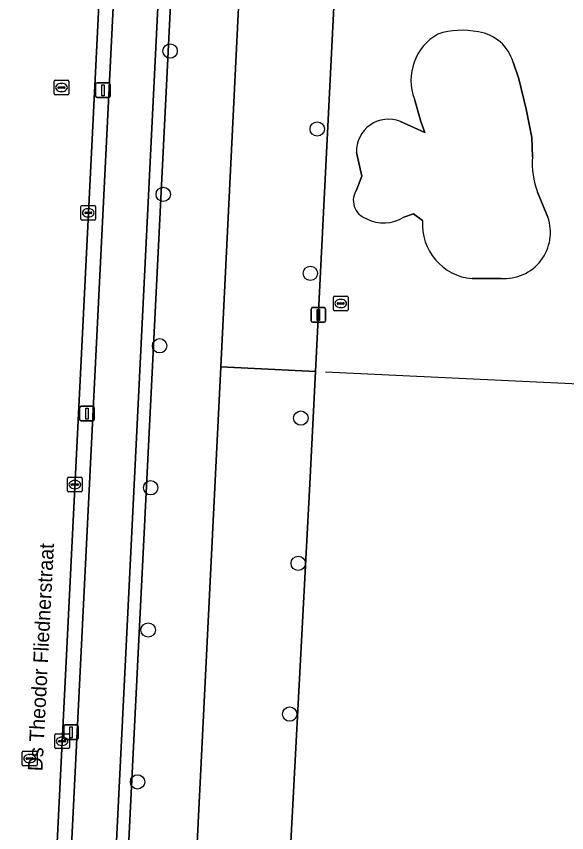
# Model space of a CAD drawing. Extents: x 161758 to 162722, y 384793 to 385405.
# Drawn here: x 162119.5 to 162156.9, y 385099.1 to 385154.7 of the extents above; entities that cross this region are included whole.
import ezdxf

# ---------------------------------------------------------------- set-up
doc = ezdxf.new("R2010")
doc.units = 0
for name, color, linetype in [('IMGEO_Boom', 7, 'Continuous'), ('IMGEO_Brandkraan', 7, 'Continuous'), ('IMGEO_Fietspad_gesloten', 7, 'Continuous'), ('IMGEO_Groenvoorziening', 7, 'Continuous'), ('IMGEO_Hek', 7, 'Continuous'), ('IMGEO_Kolk', 7, 'Continuous'), ('IMGEO_Lichtmast', 7, 'Continuous'), ('IMGEO_Openbare_ruimte_label', 7, 'Continuous'), ('IMGEO_Rijbaan_lokaal_gesloten', 7, 'Continuous'), ('IMGEO_Rioolput', 7, 'Continuous'), ('IMGEO_Verkeerseiland_open', 7, 'Continuous')]:
    doc.layers.add(name, color=color, linetype=linetype)

msp = doc.modelspace()

# ---------------------------------------------------------------- linework, layer by layer
at = {"layer": 'IMGEO_Boom'}
for centre in [(162129.924, 385152.338), (162139.937, 385147.029), (162129.455, 385142.578), (162139.469, 385137.203), (162129.208, 385132.263), (162138.822, 385127.34), (162128.599, 385122.593), (162138.645, 385117.45), (162128.431, 385112.904), (162138.061, 385107.18), (162127.706, 385102.563)]:
    msp.add_circle(centre, 0.489, dxfattribs=at)
at = {"layer": 'IMGEO_Brandkraan'}
for p, q in [((162141.037, 385134.723), (162141.037, 385135.575)), ((162141.112, 385135.649), (162141.964, 385135.649)), ((162142.038, 385135.575), (162142.038, 385134.723)), ((162141.296, 385135.143), (162141.296, 385135.155)), ((162141.734, 385135.106), (162141.336, 385135.106)), ((162141.339, 385135.192), (162141.737, 385135.192)), ((162141.525, 385135.429), (162141.55, 385135.429)), ((162141.78, 385135.155), (162141.78, 385135.143)), ((162141.964, 385134.649), (162141.112, 385134.649)), ((162141.548, 385134.869), (162141.523, 385134.869))]:
    msp.add_line(p, q, dxfattribs=at)
for points in [[(162141.037, 385134.723), (162141.037, 385135.575)], [(162141.112, 385135.649), (162141.964, 385135.649)], [(162142.038, 385135.575), (162142.038, 385134.723)], [(162141.964, 385134.649), (162141.112, 385134.649)]]:
    msp.add_lwpolyline(points, dxfattribs=at)
for centre, radius, start, end in [((162141.114, 385135.573), 0.0765, 91.552, 178.448), ((162141.114, 385135.573), 0.0765, 91.552, 178.448), ((162141.962, 385135.573), 0.0765, 1.552, 88.448), ((162141.962, 385135.573), 0.0765, 1.552, 88.448), ((162141.336, 385135.152), 0.0403, 85.8775, 175.7526), ((162141.333, 385135.142), 0.0366, 178.938, 274.7102), ((162141.737, 385135.149), 0.043, 264.8664, 352.4533), ((162141.741, 385135.154), 0.0386, 1.7309, 96.639), ((162141.114, 385134.725), 0.0765, 181.552, 268.448), ((162141.114, 385134.725), 0.0765, 181.552, 268.448), ((162141.962, 385134.725), 0.0765, 271.552, 358.448), ((162141.962, 385134.725), 0.0765, 271.552, 358.448)]:
    msp.add_arc(centre, radius, start, end, dxfattribs=at)
for centre, major_axis, ratio, start_param, end_param in [((162141.524, 385135.149), (-0.387, 0.002), 0.722429, 4.712389, 7.853982), ((162141.549, 385135.149), (-0.39, 0.002), 0.717154, 1.570796, 4.712389)]:
    msp.add_ellipse(centre, major_axis=major_axis, ratio=ratio, start_param=start_param, end_param=end_param, dxfattribs=at)
at = {"layer": 'IMGEO_Fietspad_gesloten'}
msp.add_lwpolyline([(162134.197, 385258.252), (162131.201, 385258.393), (162129.592, 385226.443), (162129.342, 385221.587), (162120.563, 385044.774), (162120.319, 385039.767), (162119.729, 385027.322), (162122.735, 385027.19), (162125.803, 385089.99), (162126.161, 385096.242), (162134.018, 385254.741)], close=True, dxfattribs=at)
at = {"layer": 'IMGEO_Groenvoorziening'}
for points in [[(162141.818, 385309.344), (162141.256, 385303.578), (162138.882, 385254.554), (162134.904, 385254.707), (162126.688, 385089.939), (162123.507, 385021.46), (162127.975, 385021.202), (162128.056, 385022.862), (162131.31, 385089.036), (162131.34, 385089.671), (162131.648, 385095.933), (162131.658, 385096.124), (162133.367, 385130.823), (162139.214, 385249.548), (162141.898, 385304.88), (162142.47, 385311.424), (162145.872, 385324.819), (162146.81, 385331.678), (162147.884, 385351.44), (162211.124, 385352.462)], [(162211.124, 385352.462), (162147.884, 385351.44), (162146.81, 385331.678), (162145.872, 385324.819), (162142.47, 385311.424), (162141.898, 385304.88), (162139.214, 385249.548), (162133.367, 385130.823), (162139.817, 385130.505), (162150.256, 385338.217), (162211.326, 385339.4)], [(162211.326, 385339.4), (162150.256, 385338.217), (162139.817, 385130.505), (162139.433, 385122.857), (162137.997, 385095.888), (162138.195, 385088.671), (162134.073, 385009.395), (162135.55, 385009.336), (162149.437, 385008.779), (162272.675, 385003.936)], [(162154.591, 385145.137), (162154.558, 385146.447), (162154.169, 385148.391), (162153.654, 385150.456), (162153.268, 385151.584)], [(162153.268, 385151.584), (162153.654, 385150.456), (162154.169, 385148.391), (162154.558, 385146.447), (162154.591, 385145.137)], [(162145.607, 385147.535), (162147.261, 385146.797), (162146.991, 385147.543), (162146.55, 385149.066)], [(162146.55, 385149.066), (162146.991, 385147.543)], [(162146.991, 385147.543), (162147.261, 385146.797), (162145.607, 385147.535)], [(162142.617, 385145.422), (162142.982, 385143.808), (162142.643, 385142.941)], [(162142.643, 385142.941), (162142.982, 385143.808), (162142.617, 385145.422)], [(162155.64, 385141.03), (162154.933, 385142.719)], [(162154.933, 385142.719), (162155.64, 385141.03)], [(162145.829, 385141.026), (162146.483, 385141.246), (162147.108, 385140.806)], [(162147.108, 385140.806), (162146.483, 385141.246), (162145.829, 385141.026)], [(162150.497, 385136.837), (162152.429, 385136.852)], [(162152.429, 385136.852), (162150.497, 385136.837)]]:
    msp.add_lwpolyline(points, dxfattribs=at)
for points in [[(162134.904, 385254.707), (162134.018, 385254.741), (162126.161, 385096.242), (162125.803, 385089.99), (162122.735, 385027.19), (162122.513, 385023.211), (162122.419, 385021.523), (162123.507, 385021.46), (162126.688, 385089.939)], [(162138.195, 385088.671), (162137.997, 385095.888), (162139.433, 385122.857), (162139.817, 385130.505), (162133.367, 385130.823), (162131.658, 385096.124), (162131.648, 385095.933), (162131.34, 385089.671), (162131.31, 385089.036), (162128.056, 385022.862), (162127.975, 385021.202), (162127.408, 385009.663), (162131.11, 385009.514), (162134.073, 385009.395)]]:
    msp.add_lwpolyline(points, close=True, dxfattribs=at)
for centre, radius, start, end in [((162149.944, 385150.345), 3.627, 119.718, 200.6486), ((162149.944, 385150.345), 3.627, 119.718, 200.6486), ((162149.805, 385148.321), 5.434, 78.2749, 107.7747), ((162149.805, 385148.321), 5.434, 78.2749, 107.7747), ((162150.493, 385150.782), 2.889, 16.1092, 81.7153), ((162150.493, 385150.782), 2.889, 16.1092, 81.7153), ((162144.783, 385145.529), 2.169, 67.6772, 182.8197), ((162144.783, 385145.529), 2.169, 67.6772, 182.8197), ((162160.279, 385144.708), 5.704, 175.6897, 200.4112), ((162160.279, 385144.708), 5.704, 175.6897, 200.4112), ((162143.715, 385142.171), 1.32, 144.3347, 251.8886), ((162143.715, 385142.171), 1.32, 144.3347, 251.8886), ((162144.474, 385143.122), 2.496, 242.0715, 302.8741), ((162144.474, 385143.122), 2.496, 242.0715, 302.8741), ((162150.805, 385140.531), 3.707, 175.7528, 265.2331), ((162150.805, 385140.531), 3.707, 175.7528, 265.2331), ((162152.671, 385139.989), 3.146, 265.5935, 19.3184), ((162152.671, 385139.989), 3.146, 265.5935, 19.3184)]:
    msp.add_arc(centre, radius, start, end, dxfattribs=at)
at = {"layer": 'IMGEO_Hek'}
for points in [[(162139.214, 385249.548), (162133.367, 385130.823)], [(162133.367, 385130.823), (162131.658, 385096.124)], [(162222.364, 385126.458), (162171.163, 385129.024), (162140.491, 385130.472)]]:
    msp.add_lwpolyline(points, dxfattribs=at)
at = {"layer": 'IMGEO_Kolk'}
for p, q in [((162123.853, 385140.892), (162123.853, 385141.744)), ((162123.928, 385141.818), (162124.78, 385141.818)), ((162124.854, 385141.744), (162124.854, 385140.892)), ((162124.112, 385141.312), (162124.112, 385141.324)), ((162124.55, 385141.275), (162124.152, 385141.275)), ((162124.155, 385141.361), (162124.553, 385141.361)), ((162124.341, 385141.598), (162124.366, 385141.598)), ((162124.596, 385141.324), (162124.596, 385141.312)), ((162124.78, 385140.818), (162123.928, 385140.818)), ((162124.364, 385141.038), (162124.339, 385141.038)), ((162123.013, 385123.309), (162123.865, 385123.309)), ((162122.938, 385122.383), (162122.938, 385123.235)), ((162123.197, 385122.803), (162123.197, 385122.815)), ((162123.635, 385122.766), (162123.237, 385122.766)), ((162123.24, 385122.852), (162123.638, 385122.852)), ((162123.426, 385123.089), (162123.451, 385123.089)), ((162123.681, 385122.815), (162123.681, 385122.803)), ((162123.939, 385123.235), (162123.939, 385122.383)), ((162123.865, 385122.309), (162123.013, 385122.309)), ((162123.449, 385122.529), (162123.424, 385122.529)), ((162122.067, 385104.904), (162122.067, 385105.756)), ((162122.142, 385105.83), (162122.994, 385105.83)), ((162122.555, 385105.61), (162122.58, 385105.61)), ((162123.068, 385105.756), (162123.068, 385104.904)), ((162122.326, 385105.324), (162122.326, 385105.336)), ((162122.764, 385105.287), (162122.366, 385105.287)), ((162122.369, 385105.373), (162122.767, 385105.373)), ((162122.578, 385105.05), (162122.553, 385105.05)), ((162122.81, 385105.336), (162122.81, 385105.324)), ((162122.994, 385104.83), (162122.142, 385104.83))]:
    msp.add_line(p, q, dxfattribs=at)
for points in [[(162123.853, 385140.892), (162123.853, 385141.744)], [(162123.928, 385141.818), (162124.78, 385141.818)], [(162124.854, 385141.744), (162124.854, 385140.892)], [(162124.78, 385140.818), (162123.928, 385140.818)], [(162123.013, 385123.309), (162123.865, 385123.309)], [(162122.938, 385122.383), (162122.938, 385123.235)], [(162123.939, 385123.235), (162123.939, 385122.383)], [(162123.865, 385122.309), (162123.013, 385122.309)], [(162122.067, 385104.904), (162122.067, 385105.756)], [(162122.142, 385105.83), (162122.994, 385105.83)], [(162123.068, 385105.756), (162123.068, 385104.904)], [(162122.994, 385104.83), (162122.142, 385104.83)]]:
    msp.add_lwpolyline(points, dxfattribs=at)
for centre, radius, start, end in [((162123.93, 385141.742), 0.0765, 91.552, 178.448), ((162123.93, 385141.742), 0.0765, 91.552, 178.448), ((162124.778, 385141.742), 0.0765, 1.552, 88.448), ((162124.778, 385141.742), 0.0765, 1.552, 88.448), ((162124.152, 385141.321), 0.0403, 85.8775, 175.7526), ((162124.149, 385141.311), 0.0366, 178.938, 274.7102), ((162124.553, 385141.318), 0.043, 264.8664, 352.4533), ((162124.557, 385141.323), 0.0386, 1.7309, 96.639), ((162123.93, 385140.894), 0.0765, 181.552, 268.448), ((162123.93, 385140.894), 0.0765, 181.552, 268.448), ((162124.778, 385140.894), 0.0765, 271.552, 358.448), ((162124.778, 385140.894), 0.0765, 271.552, 358.448), ((162123.015, 385123.233), 0.0765, 91.552, 178.448), ((162123.015, 385123.233), 0.0765, 91.552, 178.448), ((162123.863, 385123.233), 0.0765, 1.552, 88.448), ((162123.863, 385123.233), 0.0765, 1.552, 88.448), ((162123.237, 385122.812), 0.0403, 85.8775, 175.7526), ((162123.234, 385122.802), 0.0366, 178.938, 274.7102), ((162123.638, 385122.809), 0.043, 264.8664, 352.4533), ((162123.642, 385122.814), 0.0386, 1.7309, 96.639), ((162123.015, 385122.385), 0.0765, 181.552, 268.448), ((162123.015, 385122.385), 0.0765, 181.552, 268.448), ((162123.863, 385122.385), 0.0765, 271.552, 358.448), ((162123.863, 385122.385), 0.0765, 271.552, 358.448), ((162122.144, 385105.754), 0.0765, 91.552, 178.448), ((162122.144, 385105.754), 0.0765, 91.552, 178.448), ((162122.992, 385105.754), 0.0765, 1.552, 88.448), ((162122.992, 385105.754), 0.0765, 1.552, 88.448), ((162122.366, 385105.333), 0.0403, 85.8775, 175.7526), ((162122.363, 385105.323), 0.0366, 178.938, 274.7102), ((162122.767, 385105.33), 0.043, 264.8664, 352.4533), ((162122.771, 385105.335), 0.0386, 1.7309, 96.639), ((162122.144, 385104.906), 0.0765, 181.552, 268.448), ((162122.144, 385104.906), 0.0765, 181.552, 268.448), ((162122.992, 385104.906), 0.0765, 271.552, 358.448), ((162122.992, 385104.906), 0.0765, 271.552, 358.448)]:
    msp.add_arc(centre, radius, start, end, dxfattribs=at)
for centre, major_axis, ratio, start_param, end_param in [((162124.34, 385141.318), (-0.387, 0.002), 0.722429, 4.712389, 7.853982), ((162124.365, 385141.318), (-0.39, 0.002), 0.717154, 1.570796, 4.712389), ((162123.425, 385122.809), (-0.387, 0.002), 0.722429, 4.712389, 7.853982), ((162123.45, 385122.809), (-0.39, 0.002), 0.717154, 1.570796, 4.712389), ((162122.554, 385105.33), (-0.387, 0.002), 0.722429, 4.712389, 7.853982), ((162122.579, 385105.33), (-0.39, 0.002), 0.717154, 1.570796, 4.712389)]:
    msp.add_ellipse(centre, major_axis=major_axis, ratio=ratio, start_param=start_param, end_param=end_param, dxfattribs=at)
at = {"layer": 'IMGEO_Lichtmast'}
for p, q in [((162124.854, 385149.272), (162124.854, 385150.072)), ((162124.854, 385150.072), (162124.854, 385149.272)), ((162124.954, 385150.172), (162125.744, 385150.172)), ((162125.744, 385150.172), (162124.954, 385150.172)), ((162125.844, 385150.072), (162125.844, 385149.272)), ((162125.844, 385149.272), (162125.844, 385150.072)), ((162125.744, 385149.172), (162124.954, 385149.172)), ((162124.954, 385149.172), (162125.744, 385149.172)), ((162139.52, 385133.963), (162139.52, 385134.763)), ((162139.52, 385134.763), (162139.52, 385133.963)), ((162139.62, 385134.863), (162140.41, 385134.863)), ((162140.41, 385134.863), (162139.62, 385134.863)), ((162140.51, 385134.763), (162140.51, 385133.963)), ((162140.51, 385133.963), (162140.51, 385134.763)), ((162140.41, 385133.863), (162139.62, 385133.863)), ((162139.62, 385133.863), (162140.41, 385133.863)), ((162123.767, 385127.246), (162123.767, 385128.046)), ((162123.767, 385128.046), (162123.767, 385127.246)), ((162123.867, 385128.146), (162124.657, 385128.146)), ((162124.657, 385128.146), (162123.867, 385128.146)), ((162124.757, 385128.046), (162124.757, 385127.246)), ((162124.757, 385127.246), (162124.757, 385128.046)), ((162124.657, 385127.146), (162123.867, 385127.146)), ((162123.867, 385127.146), (162124.657, 385127.146)), ((162122.68, 385105.54), (162122.68, 385106.34)), ((162122.68, 385106.34), (162122.68, 385105.54)), ((162122.78, 385106.44), (162123.57, 385106.44)), ((162123.57, 385106.44), (162122.78, 385106.44)), ((162123.67, 385106.34), (162123.67, 385105.54)), ((162123.67, 385105.54), (162123.67, 385106.34)), ((162123.57, 385105.44), (162122.78, 385105.44)), ((162122.78, 385105.44), (162123.57, 385105.44))]:
    msp.add_line(p, q, dxfattribs=at)
for points in [[(162125.274, 385150.047), (162125.424, 385150.047), (162125.424, 385149.297), (162125.274, 385149.297), (162125.274, 385150.047)], [(162139.94, 385134.738), (162140.09, 385134.738), (162140.09, 385133.988), (162139.94, 385133.988), (162139.94, 385134.738)], [(162124.187, 385128.021), (162124.337, 385128.021), (162124.337, 385127.271), (162124.187, 385127.271), (162124.187, 385128.021)], [(162123.1, 385106.315), (162123.25, 385106.315), (162123.25, 385105.565), (162123.1, 385105.565), (162123.1, 385106.315)]]:
    msp.add_lwpolyline(points, dxfattribs=at)
for centre, start, end in [((162124.954, 385150.072), 90, 180), ((162124.954, 385150.072), 90, 180), ((162125.744, 385150.072), 0, 90), ((162125.744, 385150.072), 360, 90), ((162124.954, 385149.272), 180, 270), ((162124.954, 385149.272), 180, 270), ((162125.744, 385149.272), 270, 0), ((162125.744, 385149.272), 270, 0), ((162139.62, 385134.763), 90, 180), ((162139.62, 385134.763), 90, 180), ((162140.41, 385134.763), 0, 90), ((162140.41, 385134.763), 360, 90), ((162139.62, 385133.963), 180, 270), ((162139.62, 385133.963), 180, 270), ((162140.41, 385133.963), 270, 0), ((162140.41, 385133.963), 270, 0), ((162123.867, 385128.046), 90, 180), ((162123.867, 385128.046), 90, 180), ((162124.657, 385128.046), 0, 90), ((162124.657, 385128.046), 360, 90), ((162123.867, 385127.246), 180, 270), ((162123.867, 385127.246), 180, 270), ((162124.657, 385127.246), 270, 0), ((162124.657, 385127.246), 270, 0), ((162122.78, 385106.34), 90, 180), ((162122.78, 385106.34), 90, 180), ((162123.57, 385106.34), 0, 90), ((162123.57, 385106.34), 360, 90), ((162122.78, 385105.54), 180, 270), ((162122.78, 385105.54), 180, 270), ((162123.57, 385105.54), 270, 0), ((162123.57, 385105.54), 270, 0)]:
    msp.add_arc(centre, 0.1, start, end, dxfattribs=at)
at = {"layer": 'IMGEO_Rijbaan_lokaal_gesloten'}
msp.add_lwpolyline([(162127.185, 385353.161), (162127.085, 385332.496), (162126.992, 385324.158), (162126.732, 385319.163), (162124.878, 385282.238), (162124.469, 385274.256), (162122.219, 385228.776), (162121.802, 385220.491), (162113.455, 385051.843), (162119.917, 385051.572), (162121.833, 385090.293), (162122.159, 385097.081), (162128.368, 385221.63)], dxfattribs=at)
at = {"layer": 'IMGEO_Rioolput'}
for p, q in [((162122.028, 385149.43), (162122.028, 385150.282)), ((162122.103, 385150.356), (162122.955, 385150.356)), ((162122.516, 385150.136), (162122.541, 385150.136)), ((162123.029, 385150.282), (162123.029, 385149.43)), ((162122.287, 385149.85), (162122.287, 385149.862)), ((162122.725, 385149.813), (162122.327, 385149.813)), ((162122.33, 385149.899), (162122.728, 385149.899)), ((162122.539, 385149.576), (162122.514, 385149.576)), ((162122.771, 385149.862), (162122.771, 385149.85)), ((162122.955, 385149.356), (162122.103, 385149.356)), ((162119.863, 385103.723), (162119.863, 385104.575)), ((162119.938, 385104.649), (162120.79, 385104.649)), ((162120.351, 385104.429), (162120.376, 385104.429)), ((162120.864, 385104.575), (162120.864, 385103.723)), ((162120.122, 385104.143), (162120.122, 385104.155)), ((162120.56, 385104.106), (162120.162, 385104.106)), ((162120.165, 385104.192), (162120.563, 385104.192)), ((162120.374, 385103.869), (162120.349, 385103.869)), ((162120.606, 385104.155), (162120.606, 385104.143)), ((162120.79, 385103.649), (162119.938, 385103.649))]:
    msp.add_line(p, q, dxfattribs=at)
for points in [[(162122.028, 385149.43), (162122.028, 385150.282)], [(162122.103, 385150.356), (162122.955, 385150.356)], [(162123.029, 385150.282), (162123.029, 385149.43)], [(162122.955, 385149.356), (162122.103, 385149.356)], [(162119.863, 385103.723), (162119.863, 385104.575)], [(162119.938, 385104.649), (162120.79, 385104.649)], [(162120.864, 385104.575), (162120.864, 385103.723)], [(162120.79, 385103.649), (162119.938, 385103.649)]]:
    msp.add_lwpolyline(points, dxfattribs=at)
for centre, radius, start, end in [((162122.105, 385150.28), 0.0765, 91.552, 178.448), ((162122.105, 385150.28), 0.0765, 91.552, 178.448), ((162122.953, 385150.28), 0.0765, 1.552, 88.448), ((162122.953, 385150.28), 0.0765, 1.552, 88.448), ((162122.105, 385149.432), 0.0765, 181.552, 268.448), ((162122.105, 385149.432), 0.0765, 181.552, 268.448), ((162122.327, 385149.859), 0.0403, 85.8775, 175.7526), ((162122.324, 385149.849), 0.0366, 178.938, 274.7102), ((162122.728, 385149.856), 0.043, 264.8664, 352.4533), ((162122.732, 385149.861), 0.0386, 1.7309, 96.639), ((162122.953, 385149.432), 0.0765, 271.552, 358.448), ((162122.953, 385149.432), 0.0765, 271.552, 358.448), ((162119.94, 385104.573), 0.0765, 91.552, 178.448), ((162119.94, 385104.573), 0.0765, 91.552, 178.448), ((162120.788, 385104.573), 0.0765, 1.552, 88.448), ((162120.788, 385104.573), 0.0765, 1.552, 88.448), ((162120.162, 385104.152), 0.0403, 85.8775, 175.7526), ((162120.159, 385104.142), 0.0366, 178.938, 274.7102), ((162120.563, 385104.149), 0.043, 264.8664, 352.4533), ((162120.567, 385104.154), 0.0386, 1.7309, 96.639), ((162119.94, 385103.725), 0.0765, 181.552, 268.448), ((162119.94, 385103.725), 0.0765, 181.552, 268.448), ((162120.788, 385103.725), 0.0765, 271.552, 358.448), ((162120.788, 385103.725), 0.0765, 271.552, 358.448)]:
    msp.add_arc(centre, radius, start, end, dxfattribs=at)
for centre, major_axis, ratio, start_param, end_param in [((162122.515, 385149.856), (-0.387, 0.002), 0.722429, 4.712389, 7.853982), ((162122.54, 385149.856), (-0.39, 0.002), 0.717154, 1.570796, 4.712389), ((162120.35, 385104.149), (-0.387, 0.002), 0.722429, 4.712389, 7.853982), ((162120.375, 385104.149), (-0.39, 0.002), 0.717154, 1.570796, 4.712389)]:
    msp.add_ellipse(centre, major_axis=major_axis, ratio=ratio, start_param=start_param, end_param=end_param, dxfattribs=at)
at = {"layer": 'IMGEO_Verkeerseiland_open'}
msp.add_lwpolyline([(162129.342, 385221.587), (162128.368, 385221.63), (162122.159, 385097.081), (162122.689, 385097.04), (162122.36, 385090.281), (162121.833, 385090.293), (162119.917, 385051.572), (162119.581, 385044.789), (162120.563, 385044.774)], close=True, dxfattribs=at)

# ---------------------------------------------------------------- texts
at = {"layer": 'IMGEO_Openbare_ruimte_label'}
msp.add_text('Ds Theodor Fliednerstraat', height=1, rotation=87.0775, dxfattribs=at).set_placement((162121.229, 385103.271))

doc.saveas('drawing.dxf')
